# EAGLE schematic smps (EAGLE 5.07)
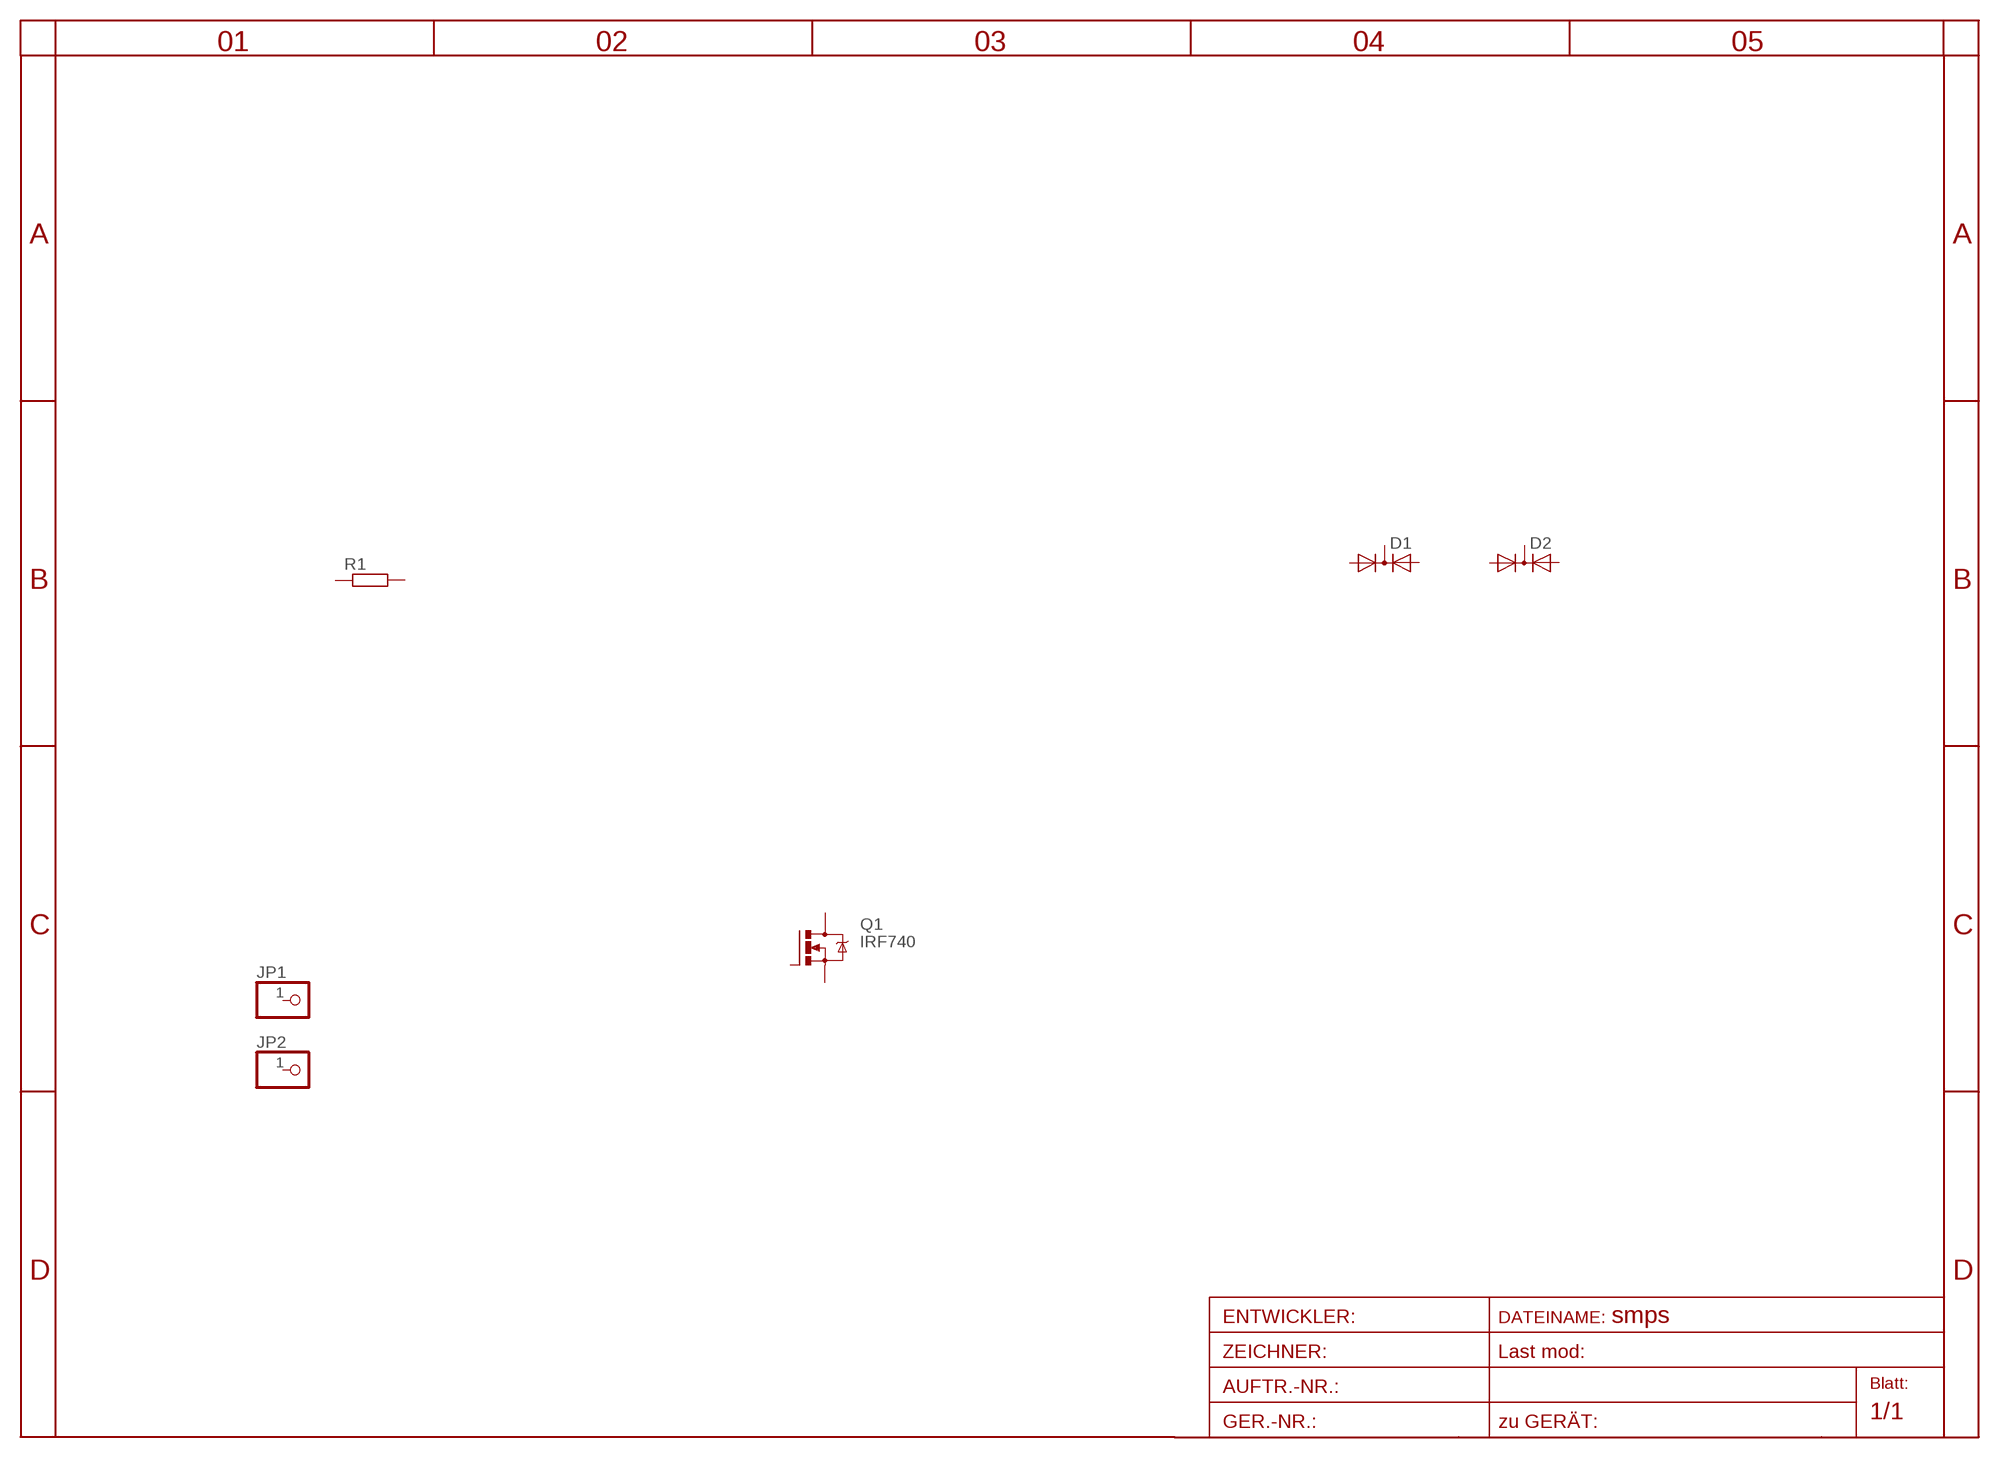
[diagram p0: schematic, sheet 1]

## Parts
D1  DIODE-2AC|CAIW220V  [IW220ABS]
D2  DIODE-2AC|CAIW220V  [IW220ABS]
JP1  PINHD-1X12MM2  [1X2MM2]
JP2  PINHD-1X12MM2  [1X2MM2]
Q1  IRF740  [TO220BV]
R1  R-EU_0204/7  [0204/7]
Unconnected: D1.A1 D1.A2 D1.C D2.A1 D2.A2 D2.C JP1.1 JP2.1 Q1.D Q1.G Q1.S R1.1 R1.2

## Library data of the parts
D1 D2 = diode:DIODE-2AC|CA: Dual DIODE Anode-Cathode|Cathode-Anode
JP1 JP2 = pinhead:PINHD-1X1: PIN HEADER
Q1 = transistor-power:IRF740: N-CHANNEL MOS FET
R1 = rcl:R-EU_: RESISTOR, European symbol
